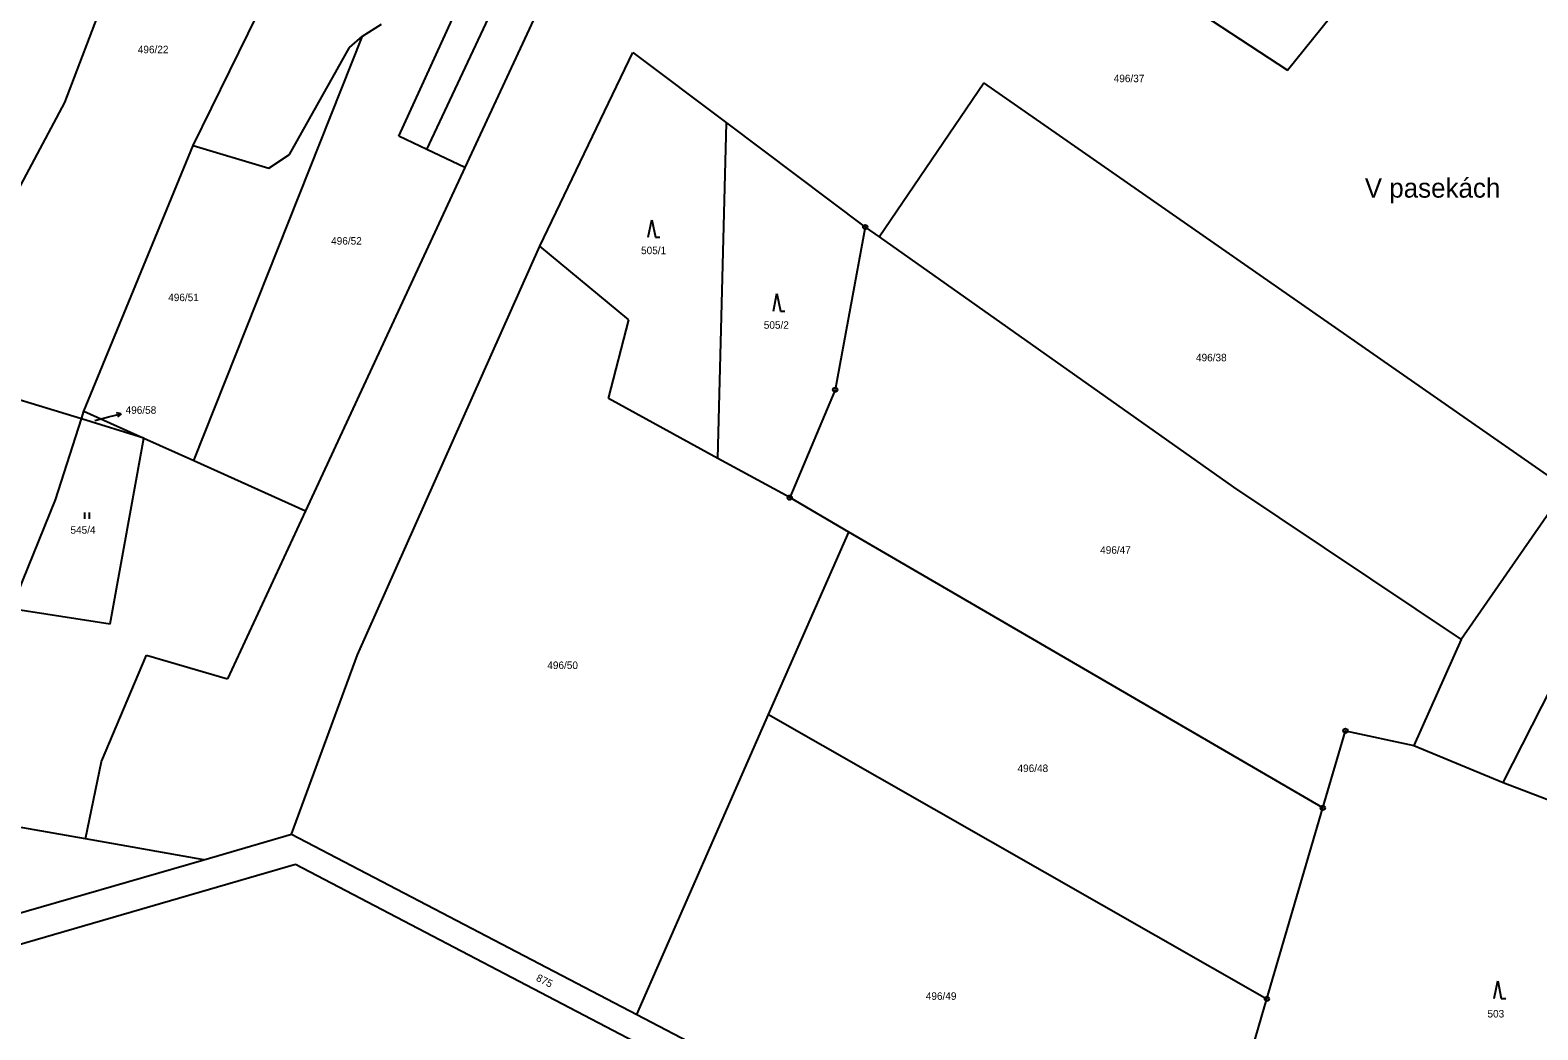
# Model space of a CAD drawing. Extents: x -791032 to -787751, y -1106872 to -1104403.
# Drawn here: x -788433.5 to -788091.4, y -1105811.1 to -1105584.4 of the extents above; entities that cross this region are included whole.
import ezdxf

# ---------------------------------------------------------------- set-up
doc = ezdxf.new("R2010")
doc.units = 0
for name, color, linetype in [('Komunikace', 7, 'Continuous'), ('Vrstva 1', 7, 'Continuous'), ('Vrstva 14', 7, 'Continuous'), ('Vrstva 16', 7, 'Continuous'), ('Vrstva 23', 7, 'Continuous'), ('Vrstva 28', 7, 'Continuous'), ('Vrstva 39', 7, 'Continuous')]:
    doc.layers.add(name, color=color, linetype=linetype)

msp = doc.modelspace()

# ---------------------------------------------------------------- linework, layer by layer
at = {"layer": 'Komunikace'}
msp.add_line((-788418.81, -1105672.93), (-788415.72, -1105672.16), dxfattribs=at)
at = {"layer": 'Vrstva 1'}
for p, q in [((-788148.21, -1105593.49), (-788100.16, -1105534.15)), ((-788343.45, -1105611.49), (-788309.15, -1105538.31)), ((-788300.66, -1105542.03), (-788334.81, -1105615.58)), ((-788193.74, -1105563.62), (-788148.21, -1105593.49)), ((-788349.8, -1105608.48), (-788331.7, -1105568.85)), ((-788396.46, -1105610.62), (-788378.27, -1105573.45)), ((-788425.57, -1105600.88), (-788416.6, -1105577.22)), ((-788396.35, -1105682.04), (-788358.03, -1105585.78)), ((-788361.04, -1105588.4), (-788358.03, -1105585.78)), ((-788358.03, -1105585.78), (-788353.78, -1105583.11)), ((-788374.63, -1105612.63), (-788361.04, -1105588.4)), ((-788317.82, -1105633.43), (-788296.69, -1105589.51)), ((-788296.69, -1105589.51), (-788275.51, -1105605.42)), ((-788240.87, -1105631.31), (-788217.12, -1105596.42)), ((-788084.96, -1105688.32), (-788217.12, -1105596.42)), ((-788458.04, -1105661.56), (-788425.57, -1105600.88)), ((-788277.41, -1105681.55), (-788275.51, -1105605.42)), ((-788275.51, -1105605.42), (-788243.99, -1105629.1)), ((-788343.45, -1105611.49), (-788349.8, -1105608.48)), ((-788421.28, -1105670.83), (-788396.46, -1105610.62)), ((-788396.46, -1105610.62), (-788379.34, -1105615.74)), ((-788379.34, -1105615.74), (-788374.63, -1105612.63)), ((-788334.81, -1105615.58), (-788343.45, -1105611.49)), ((-788334.81, -1105615.58), (-788370.97, -1105693.44)), ((-788243.99, -1105629.1), (-788250.82, -1105665.98)), ((-788243.99, -1105629.1), (-788240.87, -1105631.31)), ((-788359.2, -1105726.11), (-788317.82, -1105633.43)), ((-788297.61, -1105650.13), (-788317.82, -1105633.43)), ((-788240.87, -1105631.31), (-788160.47, -1105688.07)), ((-788302.21, -1105667.99), (-788297.61, -1105650.13)), ((-788421.85, -1105672.61), (-788458.04, -1105661.56)), ((-788277.41, -1105681.55), (-788302.21, -1105667.99)), ((-788250.82, -1105665.98), (-788261.12, -1105690.45)), ((-788421.85, -1105672.61), (-788421.28, -1105670.83)), ((-788421.28, -1105670.83), (-788407.71, -1105676.93)), ((-788427.73, -1105690.91), (-788421.85, -1105672.61)), ((-788407.71, -1105676.93), (-788421.85, -1105672.61)), ((-788415.32, -1105719.06), (-788407.71, -1105676.93)), ((-788407.71, -1105676.93), (-788396.35, -1105682.04)), ((-788261.12, -1105690.45), (-788277.41, -1105681.55)), ((-788396.35, -1105682.04), (-788370.97, -1105693.44)), ((-788160.47, -1105688.07), (-788108.78, -1105722.6)), ((-788084.96, -1105688.32), (-788108.78, -1105722.6)), ((-788437.71, -1105715.55), (-788427.73, -1105690.91)), ((-788247.72, -1105698.24), (-788261.12, -1105690.45)), ((-788370.97, -1105693.44), (-788388.66, -1105731.53)), ((-788265.92, -1105739.61), (-788247.72, -1105698.24)), ((-788140.17, -1105760.81), (-788247.72, -1105698.24)), ((-788437.71, -1105715.55), (-788415.32, -1105719.06)), ((-788108.78, -1105722.6), (-788119.49, -1105746.68)), ((-788417.31, -1105750.31), (-788407.05, -1105726.14)), ((-788407.05, -1105726.14), (-788388.66, -1105731.53)), ((-788374.15, -1105766.79), (-788359.2, -1105726.11)), ((-788099.24, -1105755.08), (-788088.27, -1105733.52)), ((-788295.85, -1105807.63), (-788265.92, -1105739.61)), ((-788265.92, -1105739.61), (-788152.86, -1105804.12)), ((-788140.17, -1105760.81), (-788135.04, -1105743.31)), ((-788135.04, -1105743.31), (-788119.49, -1105746.68)), ((-788119.49, -1105746.68), (-788099.24, -1105755.08)), ((-788420.94, -1105767.85), (-788417.31, -1105750.31)), ((-788099.24, -1105755.08), (-788078.53, -1105762.99)), ((-788420.94, -1105767.85), (-788466.21, -1105759.92)), ((-788152.86, -1105804.12), (-788140.17, -1105760.81)), ((-788394.08, -1105772.56), (-788374.15, -1105766.79)), ((-788374.15, -1105766.79), (-788295.85, -1105807.63)), ((-788394.08, -1105772.56), (-788420.94, -1105767.85)), ((-788562.53, -1105828.46), (-788373.29, -1105773.56)), ((-788550.14, -1105817.73), (-788394.08, -1105772.56)), ((-788373.29, -1105773.56), (-788198.88, -1105864.62)), ((-788163.52, -1105840.52), (-788152.86, -1105804.12)), ((-788295.85, -1105807.63), (-788199.09, -1105858.09))]:
    msp.add_line(p, q, dxfattribs=at)
at = {"layer": 'Vrstva 16'}
for p, q in [((-788415.72, -1105672.16), (-788412.809, -1105671.432)), ((-788412.809, -1105671.432), (-788413.9, -1105671.189)), ((-788412.809, -1105671.432), (-788413.658, -1105672.16))]:
    msp.add_line(p, q, dxfattribs=at)
at = {"layer": 'Vrstva 23'}
for p, q in [((-788293.21, -1105631.42), (-788292.41, -1105627.42)), ((-788292.41, -1105627.42), (-788291.61, -1105631.42)), ((-788291.61, -1105631.42), (-788290.61, -1105631.42)), ((-788264.82, -1105648.17), (-788264.02, -1105644.17)), ((-788264.02, -1105644.17), (-788263.22, -1105648.17)), ((-788263.22, -1105648.17), (-788262.22, -1105648.17)), ((-788421.05, -1105695.29), (-788421.05, -1105693.79)), ((-788420.05, -1105693.79), (-788420.05, -1105695.29)), ((-788101.27, -1105804), (-788100.47, -1105800)), ((-788100.47, -1105800), (-788099.67, -1105804)), ((-788099.67, -1105804), (-788098.67, -1105804))]:
    msp.add_line(p, q, dxfattribs=at)
at = {"layer": 'Vrstva 28'}
for centre, radius in [((-788243.99, -1105629.1), 0.5), ((-788243.99, -1105629.1), 0.01), ((-788250.82, -1105665.98), 0.5), ((-788250.82, -1105665.98), 0.01), ((-788261.12, -1105690.45), 0.5), ((-788261.12, -1105690.45), 0.01), ((-788135.04, -1105743.31), 0.5), ((-788135.04, -1105743.31), 0.01), ((-788140.17, -1105760.81), 0.5), ((-788140.17, -1105760.81), 0.01), ((-788152.86, -1105804.12), 0.5), ((-788152.86, -1105804.12), 0.01)]:
    msp.add_circle(centre, radius, dxfattribs=at)

# ---------------------------------------------------------------- texts
at = {"layer": 'Vrstva 14'}
for s, height, p in [('496/22', 1.7, (-788409.045, -1105589.68)), ('496/37', 1.7, (-788187.612, -1105596.24)), ('496/52', 1.7, (-788365.172, -1105633.07)), ('505/1', 1.7, (-788294.855, -1105635.24)), ('496/51', 1.7, (-788402.145, -1105645.89)), ('505/2', 1.7, (-788267.012, -1105652.15)), ('496/38', 1.7, (-788168.946, -1105659.53)), ('496/58', 0.1, (-788419.06, -1105672.93)), ('545/4', 1.7, (-788424.324, -1105698.63)), ('496/47', 1.7, (-788190.688, -1105703.17)), ('496/50', 1.7, (-788316.131, -1105729.3)), ('496/48', 1.7, (-788209.441, -1105752.67)), ('496/49', 1.7, (-788230.252, -1105804.32)), ('503', 1.7, (-788102.812, -1105808.33))]:
    msp.add_text(s, height=height, dxfattribs=at).set_placement(p)
msp.add_text('875', height=1.7, rotation=333.43497, dxfattribs=at).set_placement((-788318.83, -1105799.904))
at = {"layer": 'Vrstva 16'}
msp.add_text('496/58', height=1.7, dxfattribs=at).set_placement((-788411.81, -1105671.43))
at = {"layer": 'Vrstva 39'}
msp.add_text('V pasekách', height=4.4, dxfattribs=at).set_placement((-788130.65, -1105622.42))

doc.saveas('drawing.dxf')
